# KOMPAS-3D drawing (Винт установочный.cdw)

Views: Вид 1
Referenced files: Винт установочный.cdw
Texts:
  Винт установочный
  Ra 12,5
Dimensions and other numbers on the sheet: 28; 36; 164; 20; 207; 46; 53,12; 4; 1,7; 1:2; 1; 0; 2; 3; 5; 6; 7; 8; 9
